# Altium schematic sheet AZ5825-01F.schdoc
size 127 x 101 mm
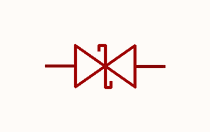
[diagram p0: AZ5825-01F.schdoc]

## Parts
D?  az5825-01f  [DFN-2L_L1.0-W0.6-P0.65-BI]  (value not drawn)

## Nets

Not connected (* = marked no-connect by the designer): D? 1(C) 2(A)

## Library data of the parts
D? = az5825-01f: 极性:双向;反向截止电压(Vrwm):5V;钳位电压:8.5V;峰值脉冲电流(Ipp):19A@8/20us;峰值脉冲功率(Ppp):140W@8/20us;击穿电压(VBR):6V;; Manufacturer: TECH PUBLIC(台舟); AddInBom: yes; ModelId: 7b44c43a15a54fb6b2a4afad776bd37d; ModelName: DFN-2L_L1.0-W0.6-0.5-P0.65-BI; ModelTransform: 40.1574,24.4094,0,0,0,0,0,0,0; Polarity: 双向; Reverse Stand-Off Voltage (Vrwm): 5V; Clamping Voltage: 8.5V; Voltage - Breakdown: 6V; Reverse Leakage Current (Ir): 80nA; Number of Channels: 单路; level of protection: IEC 61000-4-2；IEC 61000-4-4；IEC 61000-4-5; Type: ESD; Junction Capacitance: 27pF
